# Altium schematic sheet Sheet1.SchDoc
size 1651 x 889 mm; SheetNumber: 1; SheetTotal: 1
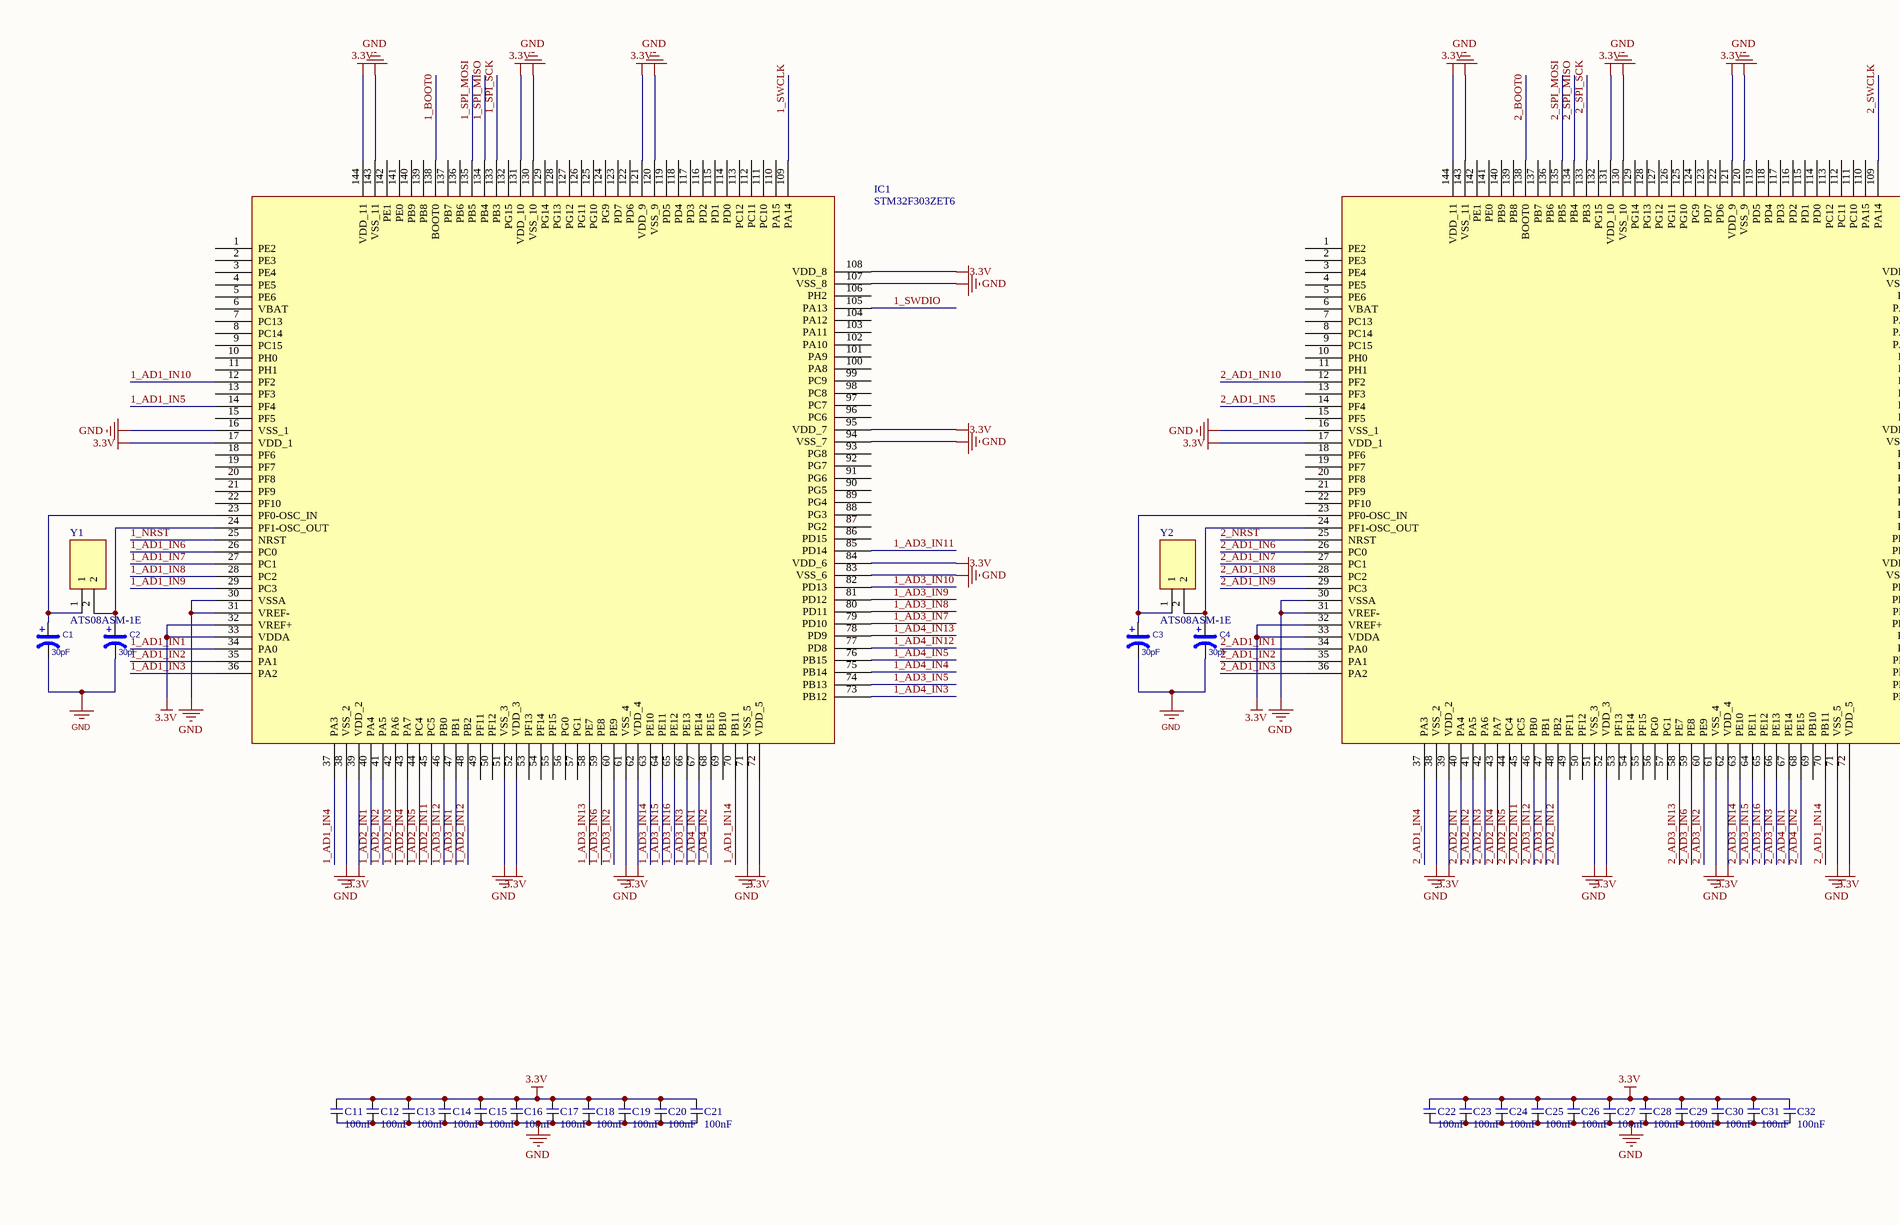
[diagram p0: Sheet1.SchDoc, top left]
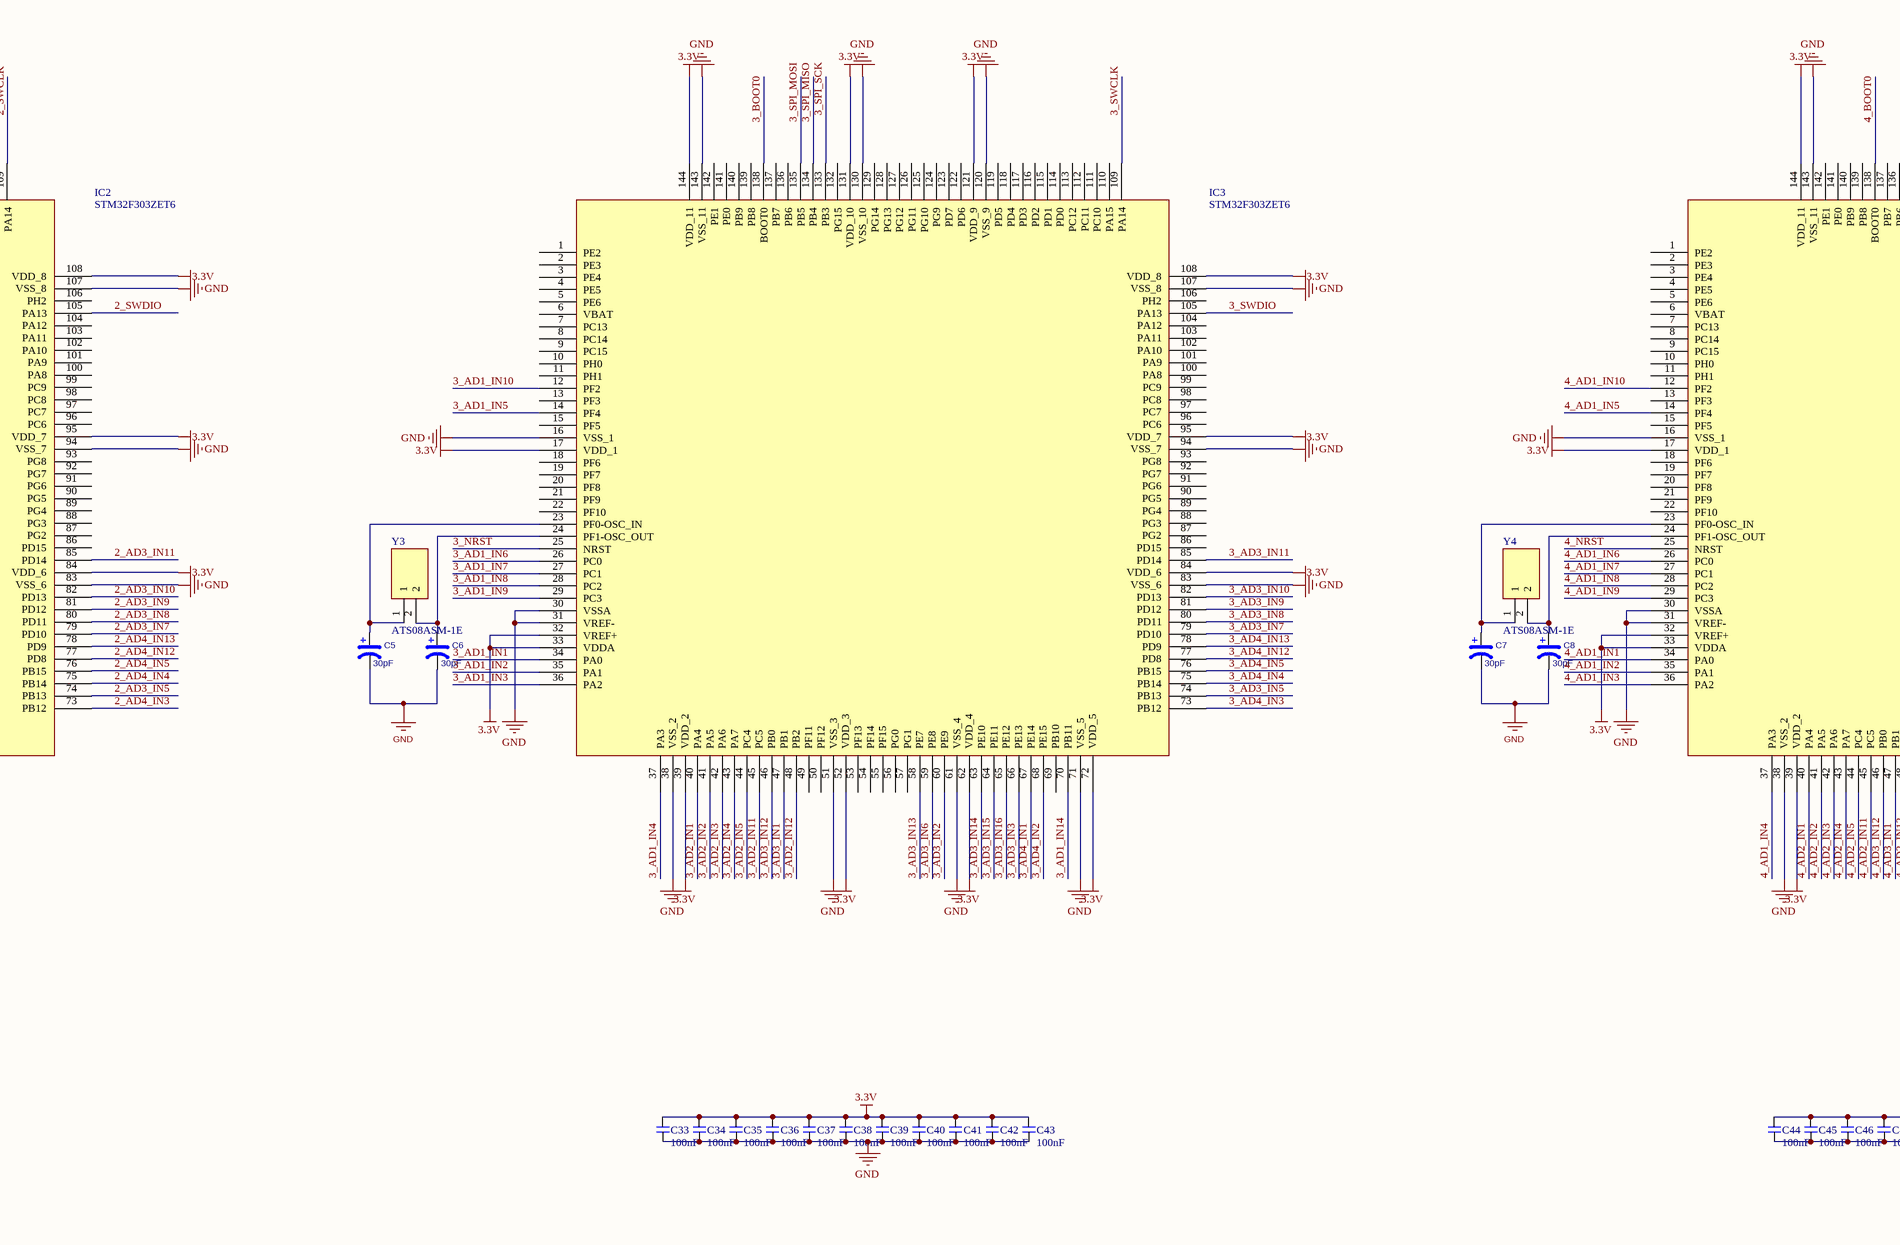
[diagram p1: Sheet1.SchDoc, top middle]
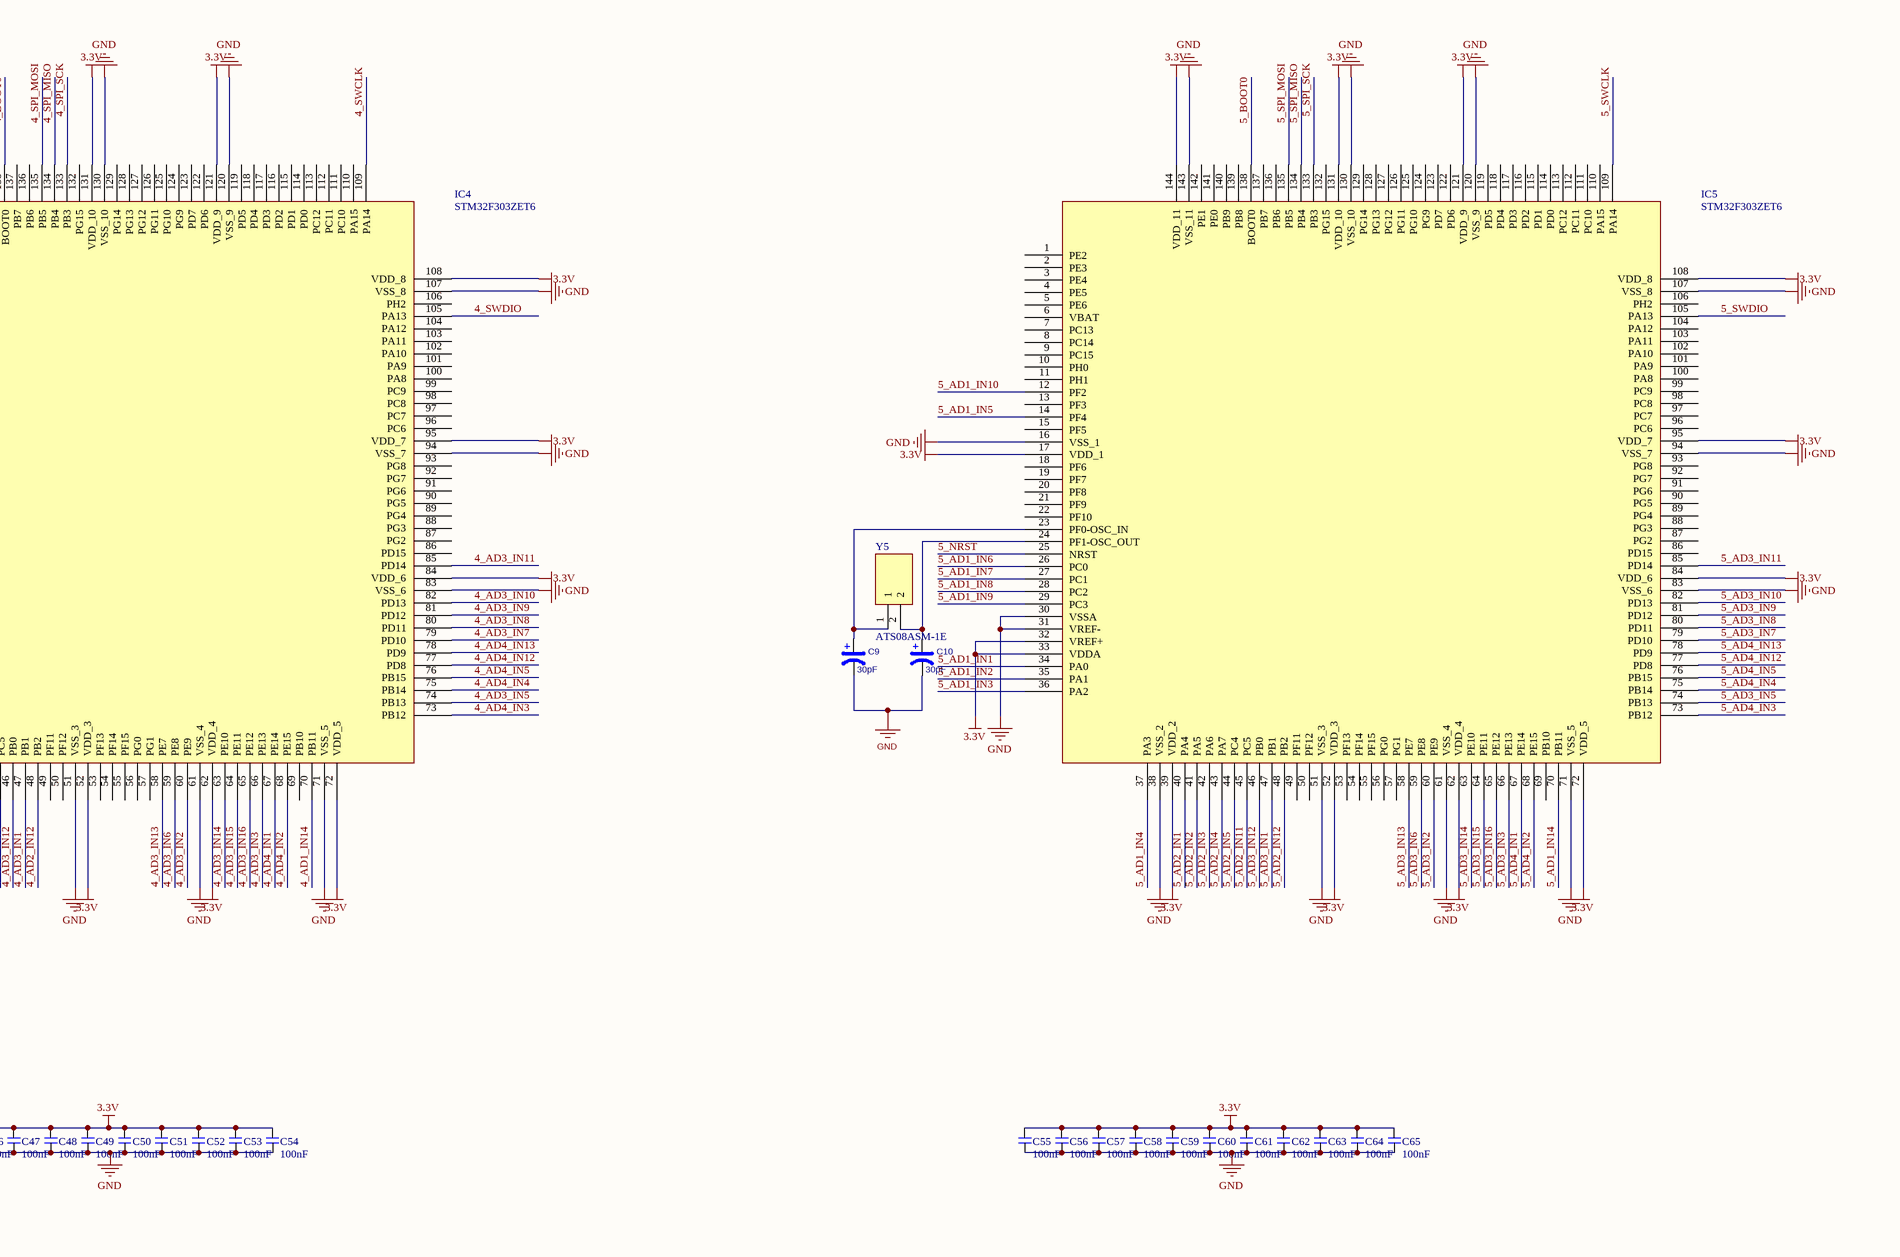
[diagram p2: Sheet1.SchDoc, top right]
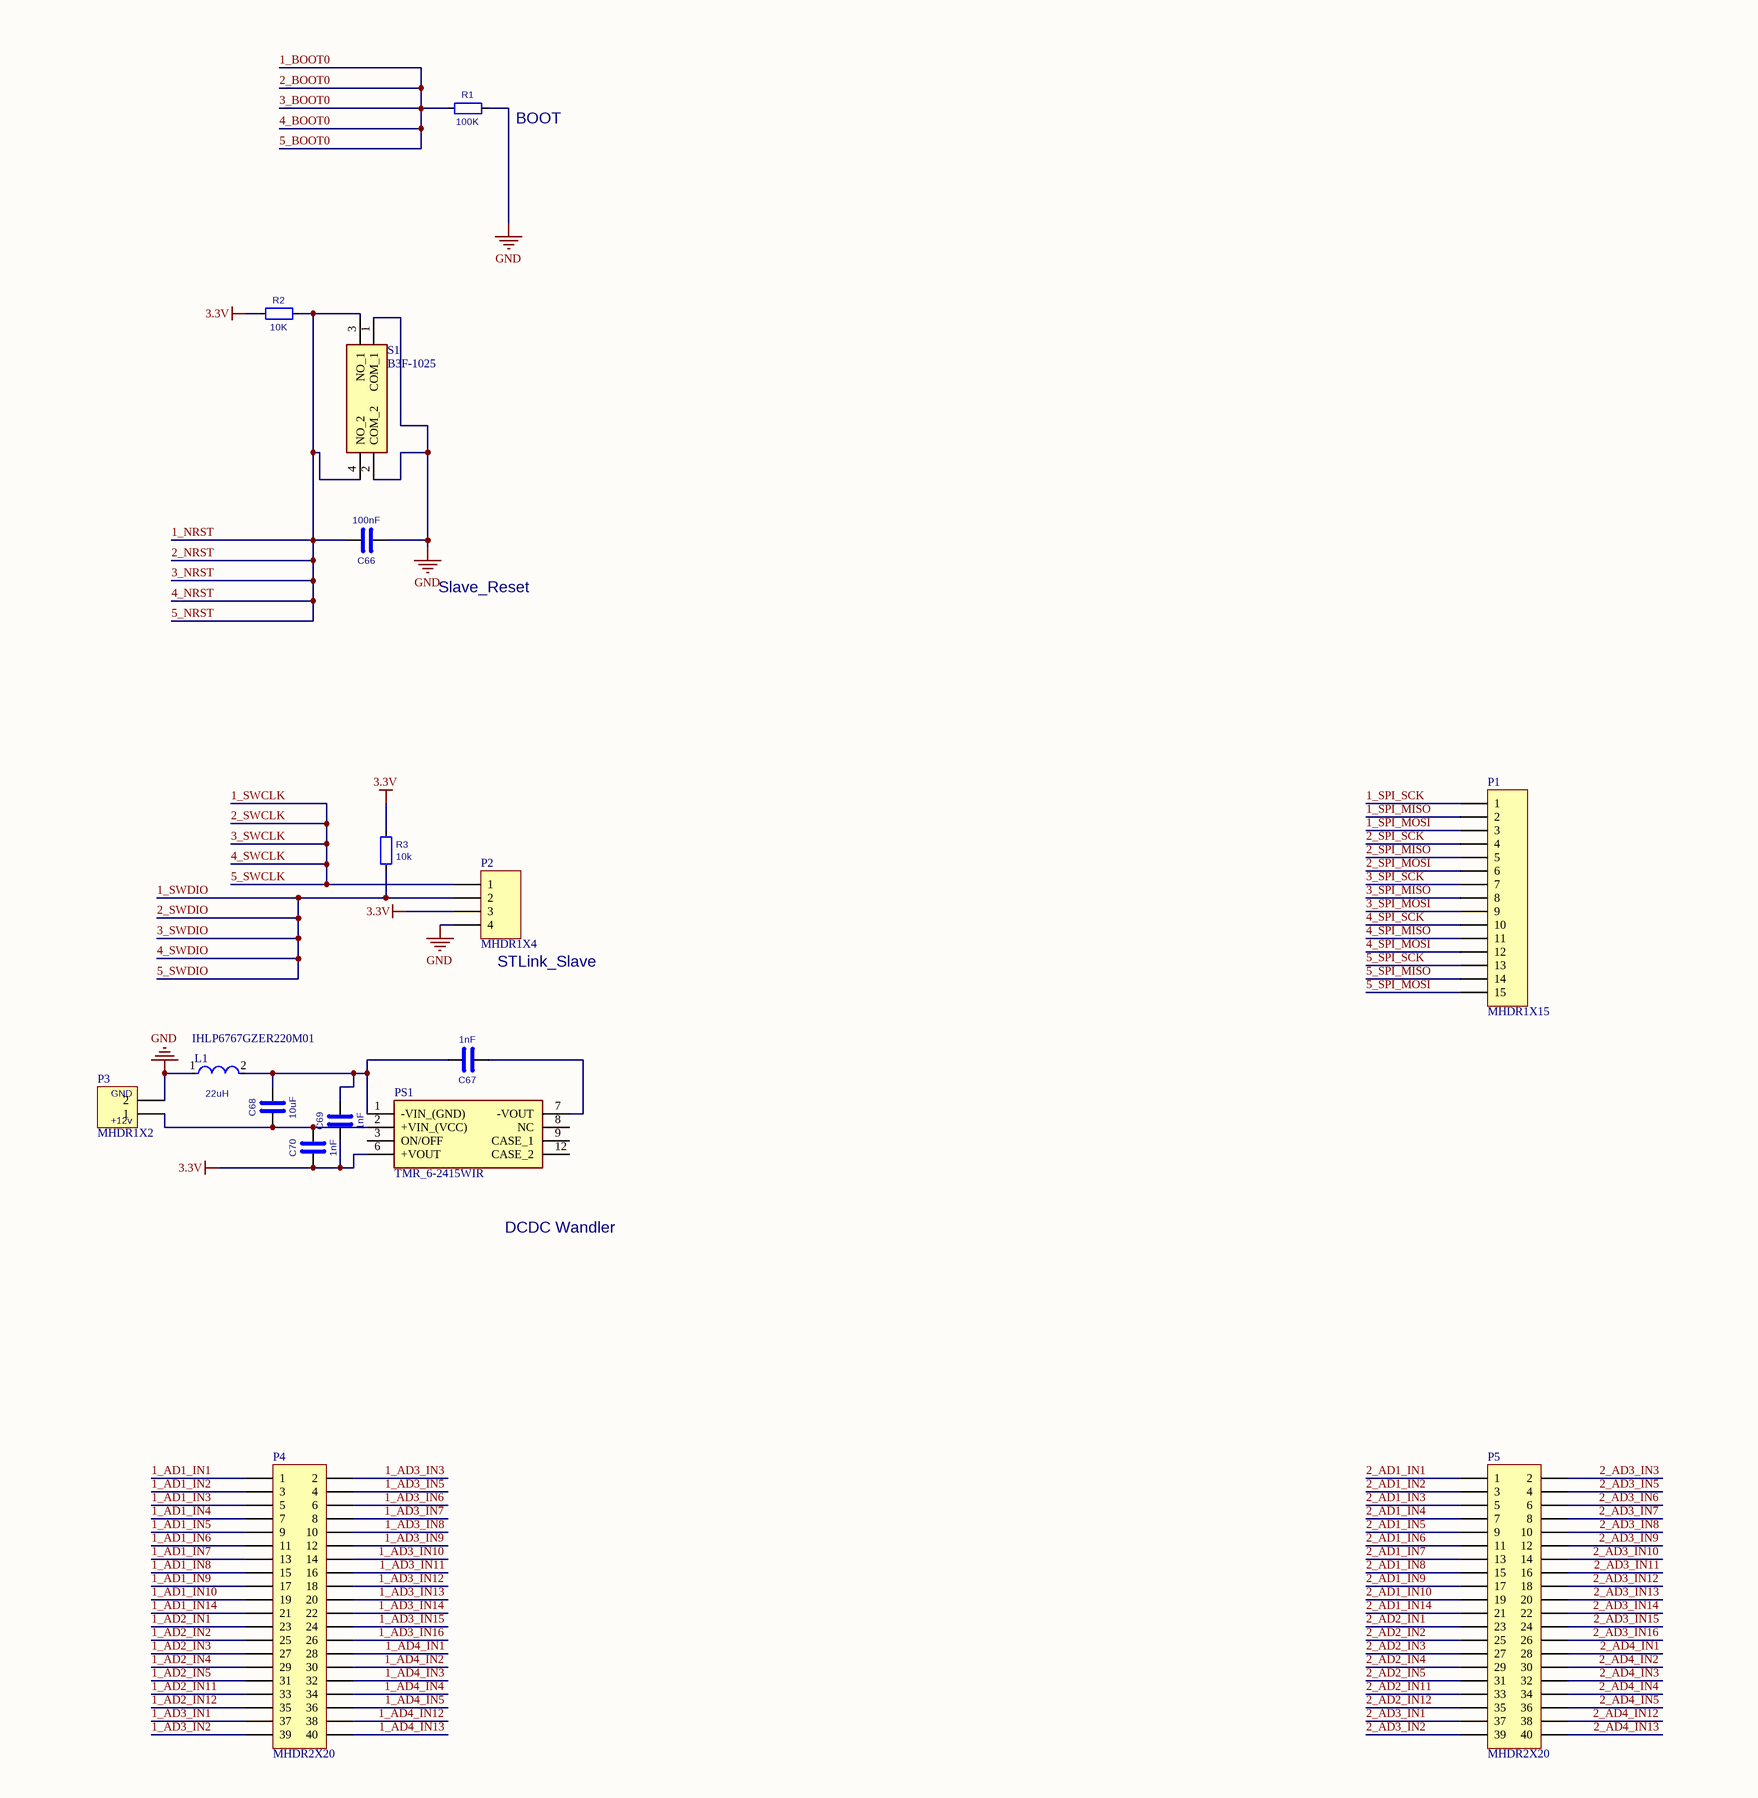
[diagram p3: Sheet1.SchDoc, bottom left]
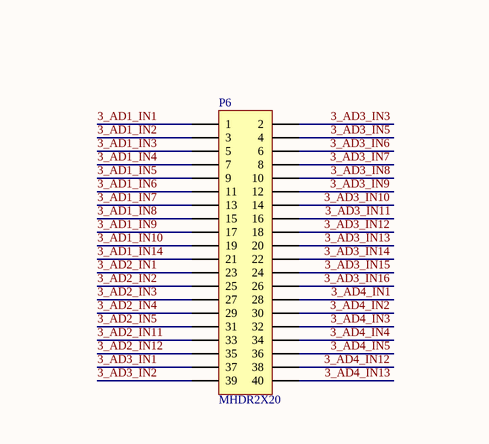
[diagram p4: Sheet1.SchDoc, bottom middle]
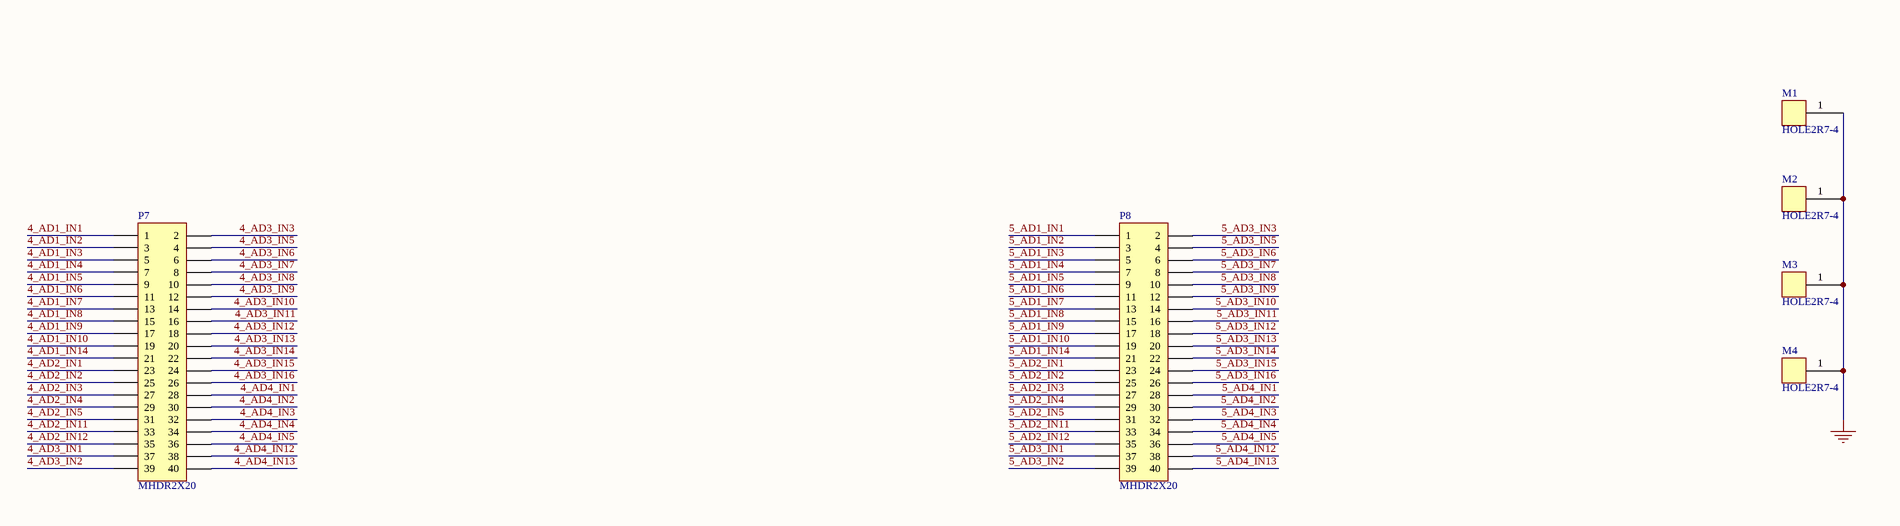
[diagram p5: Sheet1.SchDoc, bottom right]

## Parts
C1  30pF  [c0805]
C2  30pF  [c0805]
C3  30pF  [c0805]
C4  30pF  [c0805]
C5  30pF  [c0805]
C6  30pF  [c0805]
C7  30pF  [c0805]
C8  30pF  [c0805]
C9  30pF  [c0805]
C10  30pF  [c0805]
C11  100nF  [c0805]
C12  100nF  [c0805]
C13  100nF  [c0805]
C14  100nF  [c0805]
C15  100nF  [c0805]
C16  100nF  [c0805]
C17  100nF  [c0805]
C18  100nF  [c0805]
C19  100nF  [c0805]
C20  100nF  [c0805]
C21  100nF  [c0805]
C22  100nF  [c0805]
C23  100nF  [c0805]
C24  100nF  [c0805]
C25  100nF  [c0805]
C26  100nF  [c0805]
C27  100nF  [c0805]
C28  100nF  [c0805]
C29  100nF  [c0805]
C30  100nF  [c0805]
C31  100nF  [c0805]
C32  100nF  [c0805]
C33  100nF  [c0805]
C34  100nF  [c0805]
C35  100nF  [c0805]
C36  100nF  [c0805]
C37  100nF  [c0805]
C38  100nF  [c0805]
C39  100nF  [c0805]
C40  100nF  [c0805]
C41  100nF  [c0805]
C42  100nF  [c0805]
C43  100nF  [c0805]
C44  100nF  [c0805]
C45  100nF  [c0805]
C46  100nF  [c0805]
C47  100nF  [c0805]
C48  100nF  [c0805]
C49  100nF  [c0805]
C50  100nF  [c0805]
C51  100nF  [c0805]
C52  100nF  [c0805]
C53  100nF  [c0805]
C54  100nF  [c0805]
C55  100nF  [c0805]
C56  100nF  [c0805]
C57  100nF  [c0805]
C58  100nF  [c0805]
C59  100nF  [c0805]
C60  100nF  [c0805]
C61  100nF  [c0805]
C62  100nF  [c0805]
C63  100nF  [c0805]
C64  100nF  [c0805]
C65  100nF  [c0805]
C66  100nF  [c0805]
C67  1nF  [C0805]
C68  value 10uF  [C0805]  (hidden comment: 1nF)
C69  1nF  [C0805]
C70  1nF  [C0805]
IC1  STM32F303ZET6  [f303QFP50P2200X2200X160-144N]
IC2  STM32F303ZET6  [f303QFP50P2200X2200X160-144N]
IC3  STM32F303ZET6  [f303QFP50P2200X2200X160-144N]
IC4  STM32F303ZET6  [f303QFP50P2200X2200X160-144N]
IC5  STM32F303ZET6  [f303QFP50P2200X2200X160-144N]
L1  IHLP6767GZER220M01  [FP-IHLP-6767GZ-FP_3_825x1-MFG]
M1  HOLE2R7-4  [HOLE2R7-4]
M2  HOLE2R7-4  [HOLE2R7-4]
M3  HOLE2R7-4  [HOLE2R7-4]
M4  HOLE2R7-4  [HOLE2R7-4]
P1  MHDR1X15  [MHDR1X15]
P2  MHDR1X4  [MHDR1X4]
P3  MHDR1X2  [MHDR1X2]
P4  MHDR2X20  [MHDR2X20]
P5  MHDR2X20  [MHDR2X20]
P6  MHDR2X20  [MHDR2X20]
P7  MHDR2X20  [MHDR2X20]
P8  MHDR2X20  [MHDR2X20]
PS1  TMR_6-2415WIR  [TMR62410WIR]
R1  value 100K  [6-0805_N]  (hidden comment: 10K)
R2  10K  [6-0805_N]
R3  10k  [6-0805_N]
S1  B3F-1025  [B3F1025]
Y1  ATS08ASM-1E  [ATS040SM1]
Y2  ATS08ASM-1E  [ATS040SM1]
Y3  ATS08ASM-1E  [ATS040SM1]
Y4  ATS08ASM-1E  [ATS040SM1]
Y5  ATS08ASM-1E  [ATS040SM1]

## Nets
3.3V: C11.1 C12.1 C13.1 C14.1 C15.1 C16.1 C17.1 C18.1 C19.1 C20.1 C21.1 C22.1 C23.1 C24.1 C25.1 C26.1 C27.1 C28.1 C29.1 C30.1 C31.1 C32.1 C33.1 C34.1 C35.1 C36.1 C37.1 C38.1 C39.1 C40.1 C41.1 C42.1 C43.1 C44.1 C45.1 C46.1 C47.1 C48.1 C49.1 C50.1 C51.1 C52.1 C53.1 C54.1 C55.1 C56.1 C57.1 C58.1 C59.1 C60.1 C61.1 C62.1 C63.1 C64.1 C65.1 C69.2 C70.2 IC1.17(VDD_1) IC1.32(VREF+) IC1.33(VDDA) IC1.39(VDD_2) IC1.52(VDD_3) IC1.62(VDD_4) IC1.72(VDD_5) IC1.84(VDD_6) IC1.95(VDD_7) IC1.108(VDD_8) IC1.121(VDD_9) IC1.131(VDD_10) IC1.144(VDD_11) IC2.17(VDD_1) IC2.32(VREF+) IC2.33(VDDA) IC2.39(VDD_2) IC2.52(VDD_3) IC2.62(VDD_4) IC2.72(VDD_5) IC2.84(VDD_6) IC2.95(VDD_7) IC2.108(VDD_8) IC2.121(VDD_9) IC2.131(VDD_10) IC2.144(VDD_11) IC3.17(VDD_1) IC3.32(VREF+) IC3.33(VDDA) IC3.39(VDD_2) IC3.52(VDD_3) IC3.62(VDD_4) IC3.72(VDD_5) IC3.84(VDD_6) IC3.95(VDD_7) IC3.108(VDD_8) IC3.121(VDD_9) IC3.131(VDD_10) IC3.144(VDD_11) IC4.17(VDD_1) IC4.32(VREF+) IC4.33(VDDA) IC4.39(VDD_2) IC4.52(VDD_3) IC4.62(VDD_4) IC4.72(VDD_5) IC4.84(VDD_6) IC4.95(VDD_7) IC4.108(VDD_8) IC4.121(VDD_9) IC4.131(VDD_10) IC4.144(VDD_11) IC5.17(VDD_1) IC5.32(VREF+) IC5.33(VDDA) IC5.39(VDD_2) IC5.52(VDD_3) IC5.62(VDD_4) IC5.72(VDD_5) IC5.84(VDD_6) IC5.95(VDD_7) IC5.108(VDD_8) IC5.121(VDD_9) IC5.131(VDD_10) IC5.144(VDD_11) P2.3 PS1.6(+VOUT) R2.2 R3.1
GND: C1.2 C2.2 C3.2 C4.2 C5.2 C6.2 C7.2 C8.2 C9.2 C10.2 C11.2 C12.2 C13.2 C14.2 C15.2 C16.2 C17.2 C18.2 C19.2 C20.2 C21.2 C22.2 C23.2 C24.2 C25.2 C26.2 C27.2 C28.2 C29.2 C30.2 C31.2 C32.2 C33.2 C34.2 C35.2 C36.2 C37.2 C38.2 C39.2 C40.2 C41.2 C42.2 C43.2 C44.2 C45.2 C46.2 C47.2 C48.2 C49.2 C50.2 C51.2 C52.2 C53.2 C54.2 C55.2 C56.2 C57.2 C58.2 C59.2 C60.2 C61.2 C62.2 C63.2 C64.2 C65.2 C66.2 IC1.16(VSS_1) IC1.30(VSSA) IC1.31(VREF-) IC1.38(VSS_2) IC1.51(VSS_3) IC1.61(VSS_4) IC1.71(VSS_5) IC1.83(VSS_6) IC1.94(VSS_7) IC1.107(VSS_8) IC1.120(VSS_9) IC1.130(VSS_10) IC1.143(VSS_11) IC2.16(VSS_1) IC2.30(VSSA) IC2.31(VREF-) IC2.38(VSS_2) IC2.51(VSS_3) IC2.61(VSS_4) IC2.71(VSS_5) IC2.83(VSS_6) IC2.94(VSS_7) IC2.107(VSS_8) IC2.120(VSS_9) IC2.130(VSS_10) IC2.143(VSS_11) IC3.16(VSS_1) IC3.30(VSSA) IC3.31(VREF-) IC3.38(VSS_2) IC3.51(VSS_3) IC3.61(VSS_4) IC3.71(VSS_5) IC3.83(VSS_6) IC3.94(VSS_7) IC3.107(VSS_8) IC3.120(VSS_9) IC3.130(VSS_10) IC3.143(VSS_11) IC4.16(VSS_1) IC4.30(VSSA) IC4.31(VREF-) IC4.38(VSS_2) IC4.51(VSS_3) IC4.61(VSS_4) IC4.71(VSS_5) IC4.83(VSS_6) IC4.94(VSS_7) IC4.107(VSS_8) IC4.120(VSS_9) IC4.130(VSS_10) IC4.143(VSS_11) IC5.16(VSS_1) IC5.30(VSSA) IC5.31(VREF-) IC5.38(VSS_2) IC5.51(VSS_3) IC5.61(VSS_4) IC5.71(VSS_5) IC5.83(VSS_6) IC5.94(VSS_7) IC5.107(VSS_8) IC5.120(VSS_9) IC5.130(VSS_10) IC5.143(VSS_11) L1.1 M1.1 M2.1 M3.1 M4.1 P2.4 P3.2 R1.1 S1.1(COM_1) S1.2(COM_2)
1_AD1_IN1: IC1.34(PA0) P4.1
1_AD1_IN2: IC1.35(PA1) P4.3
1_AD1_IN3: IC1.36(PA2) P4.5
1_AD1_IN4: IC1.37(PA3) P4.7
1_AD1_IN5: IC1.14(PF4) P4.9
1_AD1_IN6: IC1.26(PC0) P4.11
1_AD1_IN7: IC1.27(PC1) P4.13
1_AD1_IN8: IC1.28(PC2) P4.15
1_AD1_IN9: IC1.29(PC3) P4.17
1_AD1_IN10: IC1.12(PF2) P4.19
1_AD1_IN14: IC1.70(PB11) P4.21
1_AD2_IN1: IC1.40(PA4) P4.23
1_AD2_IN2: IC1.41(PA5) P4.25
1_AD2_IN3: IC1.42(PA6) P4.27
1_AD2_IN4: IC1.43(PA7) P4.29
1_AD2_IN5: IC1.44(PC4) P4.31
1_AD2_IN11: IC1.45(PC5) P4.33
1_AD2_IN12: IC1.48(PB2) P4.35
1_AD3_IN1: IC1.47(PB1) P4.37
1_AD3_IN2: IC1.60(PE9) P4.39
1_AD3_IN3: IC1.66(PE13) P4.2
1_AD3_IN5: IC1.74(PB13) P4.4
1_AD3_IN6: IC1.59(PE8) P4.6
1_AD3_IN7: IC1.79(PD10) P4.8
1_AD3_IN8: IC1.80(PD11) P4.10
1_AD3_IN9: IC1.81(PD12) P4.12
1_AD3_IN10: IC1.82(PD13) P4.14
1_AD3_IN11: IC1.85(PD14) P4.16
1_AD3_IN12: IC1.46(PB0) P4.18
1_AD3_IN13: IC1.58(PE7) P4.20
1_AD3_IN14: IC1.63(PE10) P4.22
1_AD3_IN15: IC1.64(PE11) P4.24
1_AD3_IN16: IC1.65(PE12) P4.26
1_AD4_IN1: IC1.67(PE14) P4.28
1_AD4_IN2: IC1.68(PE15) P4.30
1_AD4_IN3: IC1.73(PB12) P4.32
1_AD4_IN4: IC1.75(PB14) P4.34
1_AD4_IN5: IC1.76(PB15) P4.36
1_AD4_IN12: IC1.77(PD8) P4.38
1_AD4_IN13: IC1.78(PD9) P4.40
1_BOOT0: IC1.138(BOOT0) IC2.138(BOOT0) IC3.138(BOOT0) IC4.138(BOOT0) IC5.138(BOOT0) R1.2  [also labelled 2_BOOT0, 3_BOOT0, 4_BOOT0, 5_BOOT0]
1_NRST: C66.1 IC1.25(NRST) IC2.25(NRST) IC3.25(NRST) IC4.25(NRST) IC5.25(NRST) R2.1 S1.3(NO_1) S1.4(NO_2)  [also labelled 2_NRST, 3_NRST, 4_NRST, 5_NRST]
1_SPI_MISO: IC1.134(PB4) P1.2
1_SPI_MOSI: IC1.135(PB5) P1.3
1_SPI_SCK: IC1.133(PB3) P1.1
1_SWCLK: IC1.109(PA14) IC2.109(PA14) IC3.109(PA14) IC4.109(PA14) IC5.109(PA14) P2.1  [also labelled 2_SWCLK, 3_SWCLK, 4_SWCLK, 5_SWCLK]
1_SWDIO: IC1.105(PA13) IC2.105(PA13) IC3.105(PA13) IC4.105(PA13) IC5.105(PA13) P2.2 R3.2  [also labelled 2_SWDIO, 3_SWDIO, 4_SWDIO, 5_SWDIO]
2_AD1_IN1: IC2.34(PA0) P5.1
2_AD1_IN2: IC2.35(PA1) P5.3
2_AD1_IN3: IC2.36(PA2) P5.5
2_AD1_IN4: IC2.37(PA3) P5.7
2_AD1_IN5: IC2.14(PF4) P5.9
2_AD1_IN6: IC2.26(PC0) P5.11
2_AD1_IN7: IC2.27(PC1) P5.13
2_AD1_IN8: IC2.28(PC2) P5.15
2_AD1_IN9: IC2.29(PC3) P5.17
2_AD1_IN10: IC2.12(PF2) P5.19
2_AD1_IN14: IC2.70(PB11) P5.21
2_AD2_IN1: IC2.40(PA4) P5.23
2_AD2_IN2: IC2.41(PA5) P5.25
2_AD2_IN3: IC2.42(PA6) P5.27
2_AD2_IN4: IC2.43(PA7) P5.29
2_AD2_IN5: IC2.44(PC4) P5.31
2_AD2_IN11: IC2.45(PC5) P5.33
2_AD2_IN12: IC2.48(PB2) P5.35
2_AD3_IN1: IC2.47(PB1) P5.37
2_AD3_IN2: IC2.60(PE9) P5.39
2_AD3_IN3: IC2.66(PE13) P5.2
2_AD3_IN5: IC2.74(PB13) P5.4
2_AD3_IN6: IC2.59(PE8) P5.6
2_AD3_IN7: IC2.79(PD10) P5.8
2_AD3_IN8: IC2.80(PD11) P5.10
2_AD3_IN9: IC2.81(PD12) P5.12
2_AD3_IN10: IC2.82(PD13) P5.14
2_AD3_IN11: IC2.85(PD14) P5.16
2_AD3_IN12: IC2.46(PB0) P5.18
2_AD3_IN13: IC2.58(PE7) P5.20
2_AD3_IN14: IC2.63(PE10) P5.22
2_AD3_IN15: IC2.64(PE11) P5.24
2_AD3_IN16: IC2.65(PE12) P5.26
2_AD4_IN1: IC2.67(PE14) P5.28
2_AD4_IN2: IC2.68(PE15) P5.30
2_AD4_IN3: IC2.73(PB12) P5.32
2_AD4_IN4: IC2.75(PB14) P5.34
2_AD4_IN5: IC2.76(PB15) P5.36
2_AD4_IN12: IC2.77(PD8) P5.38
2_AD4_IN13: IC2.78(PD9) P5.40
2_SPI_MISO: IC2.134(PB4) P1.5
2_SPI_MOSI: IC2.135(PB5) P1.6
2_SPI_SCK: IC2.133(PB3) P1.4
3_AD1_IN1: IC3.34(PA0) P6.1
3_AD1_IN2: IC3.35(PA1) P6.3
3_AD1_IN3: IC3.36(PA2) P6.5
3_AD1_IN4: IC3.37(PA3) P6.7
3_AD1_IN5: IC3.14(PF4) P6.9
3_AD1_IN6: IC3.26(PC0) P6.11
3_AD1_IN7: IC3.27(PC1) P6.13
3_AD1_IN8: IC3.28(PC2) P6.15
3_AD1_IN9: IC3.29(PC3) P6.17
3_AD1_IN10: IC3.12(PF2) P6.19
3_AD1_IN14: IC3.70(PB11) P6.21
3_AD2_IN1: IC3.40(PA4) P6.23
3_AD2_IN2: IC3.41(PA5) P6.25
3_AD2_IN3: IC3.42(PA6) P6.27
3_AD2_IN4: IC3.43(PA7) P6.29
3_AD2_IN5: IC3.44(PC4) P6.31
3_AD2_IN11: IC3.45(PC5) P6.33
3_AD2_IN12: IC3.48(PB2) P6.35
3_AD3_IN1: IC3.47(PB1) P6.37
3_AD3_IN2: IC3.60(PE9) P6.39
3_AD3_IN3: IC3.66(PE13) P6.2
3_AD3_IN5: IC3.74(PB13) P6.4
3_AD3_IN6: IC3.59(PE8) P6.6
3_AD3_IN7: IC3.79(PD10) P6.8
3_AD3_IN8: IC3.80(PD11) P6.10
3_AD3_IN9: IC3.81(PD12) P6.12
3_AD3_IN10: IC3.82(PD13) P6.14
3_AD3_IN11: IC3.85(PD14) P6.16
3_AD3_IN12: IC3.46(PB0) P6.18
3_AD3_IN13: IC3.58(PE7) P6.20
3_AD3_IN14: IC3.63(PE10) P6.22
3_AD3_IN15: IC3.64(PE11) P6.24
3_AD3_IN16: IC3.65(PE12) P6.26
3_AD4_IN1: IC3.67(PE14) P6.28
3_AD4_IN2: IC3.68(PE15) P6.30
3_AD4_IN3: IC3.73(PB12) P6.32
3_AD4_IN4: IC3.75(PB14) P6.34
3_AD4_IN5: IC3.76(PB15) P6.36
3_AD4_IN12: IC3.77(PD8) P6.38
3_AD4_IN13: IC3.78(PD9) P6.40
3_SPI_MISO: IC3.134(PB4) P1.8
3_SPI_MOSI: IC3.135(PB5) P1.9
3_SPI_SCK: IC3.133(PB3) P1.7
4_AD1_IN1: IC4.34(PA0) P7.1
4_AD1_IN2: IC4.35(PA1) P7.3
4_AD1_IN3: IC4.36(PA2) P7.5
4_AD1_IN4: IC4.37(PA3) P7.7
4_AD1_IN5: IC4.14(PF4) P7.9
4_AD1_IN6: IC4.26(PC0) P7.11
4_AD1_IN7: IC4.27(PC1) P7.13
4_AD1_IN8: IC4.28(PC2) P7.15
4_AD1_IN9: IC4.29(PC3) P7.17
4_AD1_IN10: IC4.12(PF2) P7.19
4_AD1_IN14: IC4.70(PB11) P7.21
4_AD2_IN1: IC4.40(PA4) P7.23
4_AD2_IN2: IC4.41(PA5) P7.25
4_AD2_IN3: IC4.42(PA6) P7.27
4_AD2_IN4: IC4.43(PA7) P7.29
4_AD2_IN5: IC4.44(PC4) P7.31
4_AD2_IN11: IC4.45(PC5) P7.33
4_AD2_IN12: IC4.48(PB2) P7.35
4_AD3_IN1: IC4.47(PB1) P7.37
4_AD3_IN2: IC4.60(PE9) P7.39
4_AD3_IN3: IC4.66(PE13) P7.2
4_AD3_IN5: IC4.74(PB13) P7.4
4_AD3_IN6: IC4.59(PE8) P7.6
4_AD3_IN7: IC4.79(PD10) P7.8
4_AD3_IN8: IC4.80(PD11) P7.10
4_AD3_IN9: IC4.81(PD12) P7.12
4_AD3_IN10: IC4.82(PD13) P7.14
4_AD3_IN11: IC4.85(PD14) P7.16
4_AD3_IN12: IC4.46(PB0) P7.18
4_AD3_IN13: IC4.58(PE7) P7.20
4_AD3_IN14: IC4.63(PE10) P7.22
4_AD3_IN15: IC4.64(PE11) P7.24
4_AD3_IN16: IC4.65(PE12) P7.26
4_AD4_IN1: IC4.67(PE14) P7.28
4_AD4_IN2: IC4.68(PE15) P7.30
4_AD4_IN3: IC4.73(PB12) P7.32
4_AD4_IN4: IC4.75(PB14) P7.34
4_AD4_IN5: IC4.76(PB15) P7.36
4_AD4_IN12: IC4.77(PD8) P7.38
4_AD4_IN13: IC4.78(PD9) P7.40
4_SPI_MISO: IC4.134(PB4) P1.11
4_SPI_MOSI: IC4.135(PB5) P1.12
4_SPI_SCK: IC4.133(PB3) P1.10
5_AD1_IN1: IC5.34(PA0) P8.1
5_AD1_IN2: IC5.35(PA1) P8.3
5_AD1_IN3: IC5.36(PA2) P8.5
5_AD1_IN4: IC5.37(PA3) P8.7
5_AD1_IN5: IC5.14(PF4) P8.9
5_AD1_IN6: IC5.26(PC0) P8.11
5_AD1_IN7: IC5.27(PC1) P8.13
5_AD1_IN8: IC5.28(PC2) P8.15
5_AD1_IN9: IC5.29(PC3) P8.17
5_AD1_IN10: IC5.12(PF2) P8.19
5_AD1_IN14: IC5.70(PB11) P8.21
5_AD2_IN1: IC5.40(PA4) P8.23
5_AD2_IN2: IC5.41(PA5) P8.25
5_AD2_IN3: IC5.42(PA6) P8.27
5_AD2_IN4: IC5.43(PA7) P8.29
5_AD2_IN5: IC5.44(PC4) P8.31
5_AD2_IN11: IC5.45(PC5) P8.33
5_AD2_IN12: IC5.48(PB2) P8.35
5_AD3_IN1: IC5.47(PB1) P8.37
5_AD3_IN2: IC5.60(PE9) P8.39
5_AD3_IN3: IC5.66(PE13) P8.2
5_AD3_IN5: IC5.74(PB13) P8.4
5_AD3_IN6: IC5.59(PE8) P8.6
5_AD3_IN7: IC5.79(PD10) P8.8
5_AD3_IN8: IC5.80(PD11) P8.10
5_AD3_IN9: IC5.81(PD12) P8.12
5_AD3_IN10: IC5.82(PD13) P8.14
5_AD3_IN11: IC5.85(PD14) P8.16
5_AD3_IN12: IC5.46(PB0) P8.18
5_AD3_IN13: IC5.58(PE7) P8.20
5_AD3_IN14: IC5.63(PE10) P8.22
5_AD3_IN15: IC5.64(PE11) P8.24
5_AD3_IN16: IC5.65(PE12) P8.26
5_AD4_IN1: IC5.67(PE14) P8.28
5_AD4_IN2: IC5.68(PE15) P8.30
5_AD4_IN3: IC5.73(PB12) P8.32
5_AD4_IN4: IC5.75(PB14) P8.34
5_AD4_IN5: IC5.76(PB15) P8.36
5_AD4_IN12: IC5.77(PD8) P8.38
5_AD4_IN13: IC5.78(PD9) P8.40
5_SPI_MISO: IC5.134(PB4) P1.14
5_SPI_MOSI: IC5.135(PB5) P1.15
5_SPI_SCK: IC5.133(PB3) P1.13
NetC1_1: C1.1 IC1.23(PF0-OSC_IN) Y1.1
NetC2_1: C2.1 IC1.24(PF1-OSC_OUT) Y1.2
NetC3_1: C3.1 IC2.23(PF0-OSC_IN) Y2.1
NetC4_1: C4.1 IC2.24(PF1-OSC_OUT) Y2.2
NetC5_1: C5.1 IC3.23(PF0-OSC_IN) Y3.1
NetC6_1: C6.1 IC3.24(PF1-OSC_OUT) Y3.2
NetC7_1: C7.1 IC4.23(PF0-OSC_IN) Y4.1
NetC8_1: C8.1 IC4.24(PF1-OSC_OUT) Y4.2
NetC9_1: C9.1 IC5.23(PF0-OSC_IN) Y5.1
NetC10_1: C10.1 IC5.24(PF1-OSC_OUT) Y5.2
NetC67_1: C67.1 C68.1 C69.1 L1.2 PS1.1(-VIN_(GND))
NetC67_2: C67.2 PS1.7(-VOUT)
NetC68_2: C68.2 C70.1 P3.1 PS1.2(+VIN_(VCC))

Not connected (* = marked no-connect by the designer): IC1 1(PE2) 2(PE3) 3(PE4) 4(PE5) 5(PE6) 6(VBAT) 7(PC13) 8(PC14) 9(PC15) 10(PH0) 11(PH1) 13(PF3) 15(PF5) 18(PF6) 19(PF7) 20(PF8) 21(PF9) 22(PF10) 49(PF11) 50(PF12) 53(PF13) 54(PF14) 55(PF15) 56(PG0) 57(PG1) 69(PB10) 86(PD15) 87(PG2) 88(PG3) 89(PG4) 90(PG5) 91(PG6) 92(PG7) 93(PG8) 96(PC6) 97(PC7) 98(PC8) 99(PC9) 100(PA8) 101(PA9) 102(PA10) 103(PA11) 104(PA12) 106(PH2) 110(PA15) 111(PC10) 112(PC11) 113(PC12) 114(PD0) 115(PD1) 116(PD2) 117(PD3) 118(PD4) 119(PD5) 122(PD6) 123(PD7) 124(PG9) 125(PG10) 126(PG11) 127(PG12) 128(PG13) 129(PG14) 132(PG15) 136(PB6) 137(PB7) 139(PB8) 140(PB9) 141(PE0) 142(PE1); IC2 1(PE2) 2(PE3) 3(PE4) 4(PE5) 5(PE6) 6(VBAT) 7(PC13) 8(PC14) 9(PC15) 10(PH0) 11(PH1) 13(PF3) 15(PF5) 18(PF6) 19(PF7) 20(PF8) 21(PF9) 22(PF10) 49(PF11) 50(PF12) 53(PF13) 54(PF14) 55(PF15) 56(PG0) 57(PG1) 69(PB10) 86(PD15) 87(PG2) 88(PG3) 89(PG4) 90(PG5) 91(PG6) 92(PG7) 93(PG8) 96(PC6) 97(PC7) 98(PC8) 99(PC9) 100(PA8) 101(PA9) 102(PA10) 103(PA11) 104(PA12) 106(PH2) 110(PA15) 111(PC10) 112(PC11) 113(PC12) 114(PD0) 115(PD1) 116(PD2) 117(PD3) 118(PD4) 119(PD5) 122(PD6) 123(PD7) 124(PG9) 125(PG10) 126(PG11) 127(PG12) 128(PG13) 129(PG14) 132(PG15) 136(PB6) 137(PB7) 139(PB8) 140(PB9) 141(PE0) 142(PE1); IC3 1(PE2) 2(PE3) 3(PE4) 4(PE5) 5(PE6) 6(VBAT) 7(PC13) 8(PC14) 9(PC15) 10(PH0) 11(PH1) 13(PF3) 15(PF5) 18(PF6) 19(PF7) 20(PF8) 21(PF9) 22(PF10) 49(PF11) 50(PF12) 53(PF13) 54(PF14) 55(PF15) 56(PG0) 57(PG1) 69(PB10) 86(PD15) 87(PG2) 88(PG3) 89(PG4) 90(PG5) 91(PG6) 92(PG7) 93(PG8) 96(PC6) 97(PC7) 98(PC8) 99(PC9) 100(PA8) 101(PA9) 102(PA10) 103(PA11) 104(PA12) 106(PH2) 110(PA15) 111(PC10) 112(PC11) 113(PC12) 114(PD0) 115(PD1) 116(PD2) 117(PD3) 118(PD4) 119(PD5) 122(PD6) 123(PD7) 124(PG9) 125(PG10) 126(PG11) 127(PG12) 128(PG13) 129(PG14) 132(PG15) 136(PB6) 137(PB7) 139(PB8) 140(PB9) 141(PE0) 142(PE1); IC4 1(PE2) 2(PE3) 3(PE4) 4(PE5) 5(PE6) 6(VBAT) 7(PC13) 8(PC14) 9(PC15) 10(PH0) 11(PH1) 13(PF3) 15(PF5) 18(PF6) 19(PF7) 20(PF8) 21(PF9) 22(PF10) 49(PF11) 50(PF12) 53(PF13) 54(PF14) 55(PF15) 56(PG0) 57(PG1) 69(PB10) 86(PD15) 87(PG2) 88(PG3) 89(PG4) 90(PG5) 91(PG6) 92(PG7) 93(PG8) 96(PC6) 97(PC7) 98(PC8) 99(PC9) 100(PA8) 101(PA9) 102(PA10) 103(PA11) 104(PA12) 106(PH2) 110(PA15) 111(PC10) 112(PC11) 113(PC12) 114(PD0) 115(PD1) 116(PD2) 117(PD3) 118(PD4) 119(PD5) 122(PD6) 123(PD7) 124(PG9) 125(PG10) 126(PG11) 127(PG12) 128(PG13) 129(PG14) 132(PG15) 136(PB6) 137(PB7) 139(PB8) 140(PB9) 141(PE0) 142(PE1); IC5 1(PE2) 2(PE3) 3(PE4) 4(PE5) 5(PE6) 6(VBAT) 7(PC13) 8(PC14) 9(PC15) 10(PH0) 11(PH1) 13(PF3) 15(PF5) 18(PF6) 19(PF7) 20(PF8) 21(PF9) 22(PF10) 49(PF11) 50(PF12) 53(PF13) 54(PF14) 55(PF15) 56(PG0) 57(PG1) 69(PB10) 86(PD15) 87(PG2) 88(PG3) 89(PG4) 90(PG5) 91(PG6) 92(PG7) 93(PG8) 96(PC6) 97(PC7) 98(PC8) 99(PC9) 100(PA8) 101(PA9) 102(PA10) 103(PA11) 104(PA12) 106(PH2) 110(PA15) 111(PC10) 112(PC11) 113(PC12) 114(PD0) 115(PD1) 116(PD2) 117(PD3) 118(PD4) 119(PD5) 122(PD6) 123(PD7) 124(PG9) 125(PG10) 126(PG11) 127(PG12) 128(PG13) 129(PG14) 132(PG15) 136(PB6) 137(PB7) 139(PB8) 140(PB9) 141(PE0) 142(PE1); PS1 3(ON/OFF) 8(NC) 9(CASE_1) 12(CASE_2)

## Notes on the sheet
- (near R1) BOOT
- Slave_Reset
- (near P2) STLink_Slave
- (near P3) GND
- (near L1) 22uH
- (near P3) +12v
- DCDC Wandler

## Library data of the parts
C1-C10 = CP1
C11-C65 = Cap_0805
C66-C70 = C
L1 = CMP-02424-000149-1: Commercial Inductors, High Saturation Series 22uH 11A 26.5mΩ 20%; Core Material: Metal; Shielding: Shielded; Saturation Current: 23A; Self Resonant Frequency: 2MHz; Test Frequency: 100kHz; DC Resistance (DCR): 26.5mR
P1 = MHDR1X15: Header, 15-Pin
P2 = MHDR1X4: Header, 4-Pin
P3 = MHDR1X2: Header, 2-Pin
P4-P8 = MHDR2X20: Header, 20-Pin, Dual row
PS1 = TMR_6-2415WIR: Power Supply; Manufacturer_Name: Traco Power; Manufacturer_Part_Number: TMR 6-2415WIR
R1-R3 = R
S1 = B3F-1025: Switch; Manufacturer_Name: Omron Electronics
Y1-Y5 = ATS08ASM-1E: Crystal or Oscillator; Manufacturer_Name: CTS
